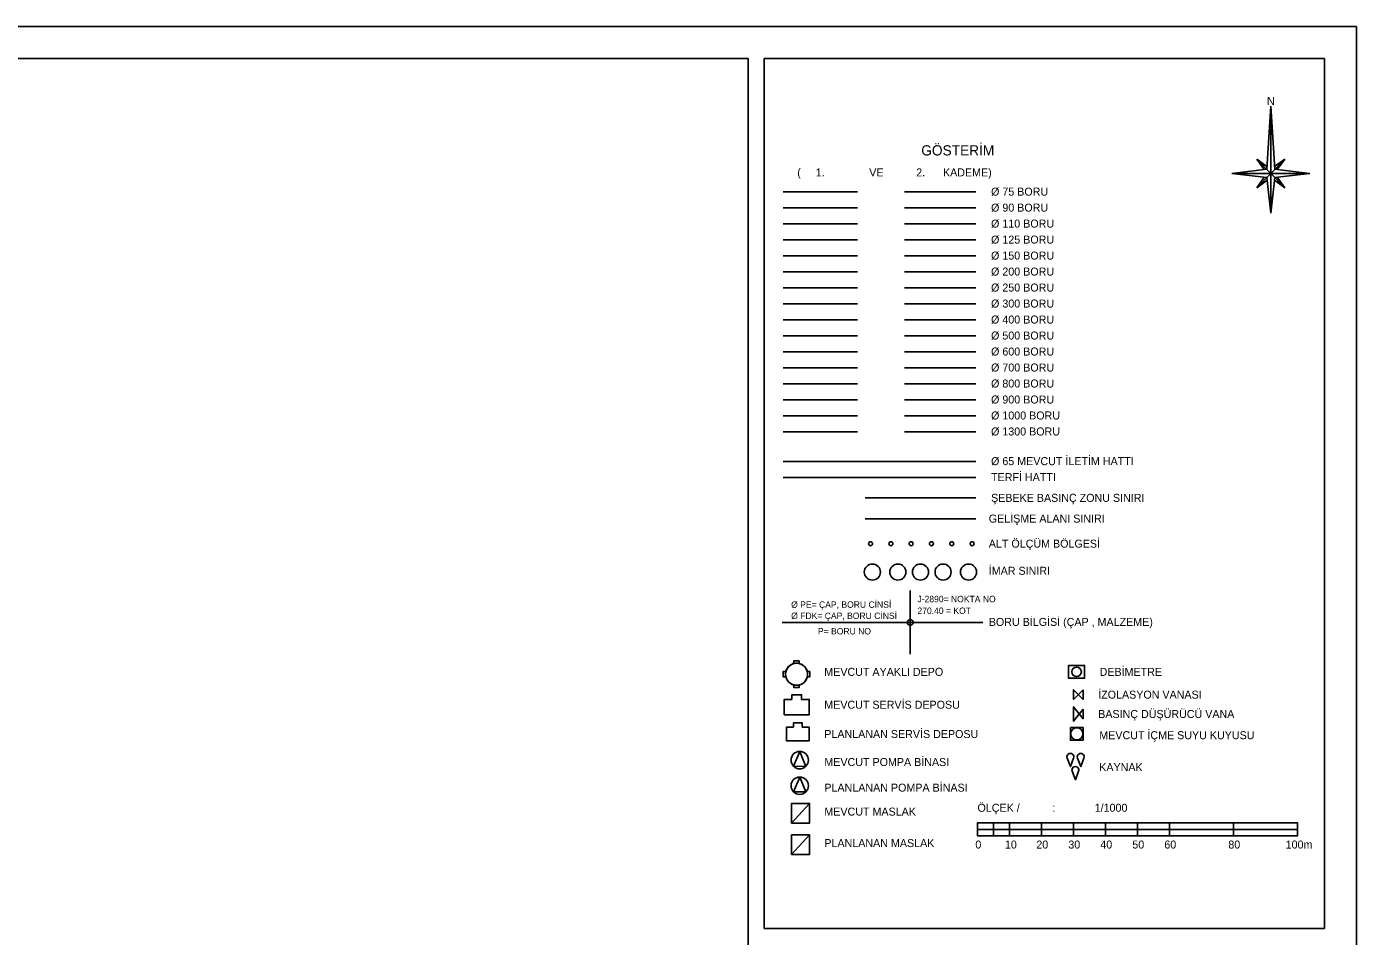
# Model space of a CAD drawing. Extents: x 314 to 1145, y -10 to 574.
# Drawn here: x 729.5 to 1145, y 289.5 to 574 of the extents above; entities that cross this region are included whole.
import ezdxf

# ---------------------------------------------------------------- set-up
doc = ezdxf.new("R2010")
doc.units = 0
for name, color, linetype in [('00-SERVIS_DEPO', 7, 'Continuous'), ('00_ALT_BOLGE_SINIRI', 7, 'Continuous'), ('00_GELISME_SINIRI', 7, 'Continuous'), ('00_IMAR SINIRI', 7, 'Continuous'), ('00_KAYNAK', 7, 'Continuous'), ('00_MASLAK', 7, 'Continuous'), ('00_MEVCUT ILETIM HATTI', 7, 'Continuous'), ('00_TERFİ HATTI', 7, 'Continuous'), ('00_TM', 7, 'Continuous'), ('00_VANA', 7, 'Continuous'), ('01_BORU_75', 7, 'Continuous'), ('02_BORU_100', 7, 'Continuous'), ('03_BORU_150', 7, 'Continuous'), ('04_BORU_200', 7, 'Continuous'), ('05_BORU_250', 7, 'Continuous'), ('06_BORU_300', 7, 'Continuous'), ('07_BORU_400', 7, 'Continuous'), ('08_BORU_500', 7, 'Continuous'), ('09_BORU_600', 7, 'Continuous'), ('10_BORU_700', 7, 'Continuous'), ('11_BORU_800', 7, 'Continuous'), ('125_boru', 7, 'Continuous'), ('12_BORU_900', 7, 'Continuous'), ('13_BORU_1000', 7, 'Continuous'), ('14_BORU_1300', 7, 'Continuous'), ('BETON-25', 7, 'Continuous'), ('BETON-60', 7, 'Continuous'), ('Boru Bilgisi', 7, 'Continuous'), ('Default', 7, 'Continuous'), ('Lejand', 7, 'Continuous'), ('Level 50', 7, 'Continuous'), ('Level 51', 7, 'Continuous'), ('Level 52', 7, 'Continuous'), ('ScaleBar-20', 7, 'Continuous'), ('ScaleBar-25', 7, 'Continuous'), ('SEMBOL-10', 7, 'Continuous'), ('SEMBOL-30', 7, 'Continuous'), ('YAZI-25', 7, 'Continuous'), ('YAZI-40', 7, 'Continuous'), ('ŞEBEKE BASINC ZON SINIRI', 7, 'Continuous')]:
    doc.layers.add(name, color=color, linetype=linetype)

# ---------------------------------------------------------------- blocks, each defined once
blk = doc.blocks.new('junction_1')
at = {"layer": '00_NODE'}
for start, end in [(45, 225), (45, 225), (225, 45), (225, 45)]:
    blk.add_arc((0, -0.02), 0.914, start, end, dxfattribs=at)
blk = doc.blocks.new('junction_2')
at = {"layer": 'Default'}
blk.add_blockref('junction_1', (0, 0), dxfattribs=at)
blk = doc.blocks.new('A$C32CF5DD8')
at = {"layer": '00_KAYNAK'}
for points in [[(35, 179), (0, 264), (-30, 179)], [(-30, 179), (0, 264), (35, 179)], [(-20, 47), (-54, 132), (-84, 47)], [(-84, 47), (-54, 132), (-20, 47)], [(84, 47), (49, 132), (20, 47)], [(20, 47), (49, 132), (84, 47)]]:
    blk.add_lwpolyline(points, dxfattribs=at)
for centre in [(2, 167), (2, 167), (-52, 35), (-52, 35), (52, 35), (52, 35)]:
    blk.add_arc(centre, 34.6, 159.3514, 20.6486, dxfattribs=at)

msp = doc.modelspace()

# ---------------------------------------------------------------- linework, layer by layer
at = {"layer": '00-SERVIS_DEPO'}
for p, q in [((969.27, 374.86), (969.27, 375.68)), ((969.27, 375.68), (970.87, 375.68)), ((970.87, 374.86), (970.87, 375.68)), ((965.89, 372.29), (966.7, 372.29)), ((965.89, 370.69), (965.89, 372.29)), ((965.89, 370.69), (966.7, 370.69)), ((973.44, 372.29), (974.26, 372.29)), ((973.44, 370.69), (974.26, 370.69)), ((974.26, 372.29), (974.26, 370.69)), ((969.27, 367.31), (969.27, 368.13)), ((969.27, 367.31), (970.87, 367.31)), ((970.87, 367.31), (970.87, 368.13))]:
    msp.add_line(p, q, dxfattribs=at)
for points in [[(970.87, 375.68), (969.27, 375.68), (969.27, 374.86)], [(970.87, 374.86), (970.87, 375.68)], [(966.7, 372.29), (965.89, 372.29), (965.89, 370.69), (966.7, 370.69)], [(974.26, 372.29), (973.44, 372.29)], [(973.44, 370.69), (974.26, 370.69), (974.26, 372.29)], [(969.27, 368.13), (969.27, 367.31), (970.87, 367.31), (970.87, 368.13)], [(968.62, 363.6), (966.24, 363.6), (966.24, 358.79), (974.03, 358.79), (974.03, 363.6), (971.65, 363.6), (971.65, 365.07), (968.62, 365.07), (968.62, 363.6)], [(968.62, 363.6), (966.24, 363.6), (966.24, 358.79), (974.03, 358.79), (974.03, 363.6), (971.65, 363.6), (971.65, 365.07), (968.62, 365.07), (968.62, 363.6)], [(969.11, 354.95), (966.97, 354.95), (966.97, 350.62), (973.98, 350.62), (973.98, 354.95), (971.84, 354.95), (971.84, 356.28), (969.11, 356.28), (969.11, 354.95)]]:
    msp.add_lwpolyline(points, dxfattribs=at)
msp.add_circle((970.07, 371.49), 3.46, dxfattribs=at)
for start, end in [(13.3637, 180), (76.6363, 103.3637), (166.6363, 180), (180, 193.3637), (180, 193.3637), (193.3637, 360), (360, 13.3637), (360, 13.3637), (346.6363, 0), (256.6363, 283.3637)]:
    msp.add_arc((970.07, 371.49), 3.46, start, end, dxfattribs=at)
at = {"layer": '00_ALT_BOLGE_SINIRI'}
for centre, start, end in [((993.19, 412.29), 0, 180), ((993.19, 412.29), 180, 0), ((999.54, 412.29), 0, 180), ((999.54, 412.29), 180, 0), ((1005.88, 412.29), 0, 180), ((1005.88, 412.29), 180, 0), ((1012.23, 412.29), 0, 180), ((1012.23, 412.29), 180, 0), ((1018.58, 412.29), 0, 180), ((1018.58, 412.29), 180, 0), ((1024.93, 412.29), 0, 180), ((1024.93, 412.29), 180, 0)]:
    msp.add_arc(centre, 0.625, start, end, dxfattribs=at)
at = {"layer": '00_GELISME_SINIRI'}
msp.add_line((991.47, 420.1), (1026.14, 420.1), dxfattribs=at)
at = {"layer": '00_IMAR SINIRI'}
for centre in [(993.77, 403.43), (1001.73, 403.43), (1008.79, 403.43), (1015.86, 403.43), (1023.82, 403.43)]:
    msp.add_circle(centre, 2.52, dxfattribs=at)
at = {"layer": '00_MASLAK'}
for p, q in [((974.12, 331.1), (968.54, 324.96)), ((968.54, 324.96), (974.12, 331.1)), ((968.54, 315.12), (974.12, 321.26))]:
    msp.add_line(p, q, dxfattribs=at)
msp.add_lwpolyline([(968.54, 324.96), (974.12, 324.96), (974.12, 331.1)], dxfattribs=at)
for points in [[(968.54, 324.96), (974.12, 324.96), (974.12, 331.1), (968.54, 331.1)], [(968.54, 315.12), (974.12, 315.12), (974.12, 321.26), (968.54, 321.26)]]:
    msp.add_lwpolyline(points, close=True, dxfattribs=at)
at = {"layer": '00_MEVCUT ILETIM HATTI'}
msp.add_line((965.89, 438.05), (1026.14, 438.05), dxfattribs=at)
at = {"layer": '00_TERFİ HATTI'}
msp.add_line((965.89, 433.05), (1026.14, 433.05), dxfattribs=at)
at = {"layer": '00_TM'}
for points in [[(972.98, 342.68), (971.05, 347.36), (969.12, 342.72), (972.98, 342.68)], [(972.98, 342.68), (971.05, 347.36), (969.12, 342.72), (972.98, 342.68)], [(972.98, 334.67), (971.05, 339.35), (969.12, 334.71), (972.98, 334.67)]]:
    msp.add_lwpolyline(points, dxfattribs=at)
for centre in [(971.07, 344.63), (971.07, 336.62)]:
    msp.add_circle(centre, 2.73, dxfattribs=at)
at = {"layer": '00_VANA'}
for points in [[(1059.62, 366.61), (1056.62, 363.61), (1056.62, 366.61), (1059.62, 363.61), (1059.62, 366.61)], [(1059.62, 360.55), (1056.62, 356.8), (1056.62, 361.3), (1059.62, 357.55), (1059.62, 360.55)]]:
    msp.add_lwpolyline(points, dxfattribs=at)
at = {"layer": '01_BORU_75'}
for p, q in [((965.89, 522.33), (989.08, 522.33)), ((1003.79, 522.33), (1026.14, 522.33))]:
    msp.add_line(p, q, dxfattribs=at)
at = {"layer": '02_BORU_100'}
for p, q in [((965.89, 517.33), (989.08, 517.33)), ((1003.79, 517.33), (1026.14, 517.33)), ((965.89, 512.33), (989.08, 512.33)), ((1003.79, 512.33), (1026.14, 512.33))]:
    msp.add_line(p, q, dxfattribs=at)
at = {"layer": '03_BORU_150'}
for p, q in [((965.89, 502.33), (989.08, 502.33)), ((1003.79, 502.33), (1026.14, 502.33))]:
    msp.add_line(p, q, dxfattribs=at)
at = {"layer": '04_BORU_200'}
for p, q in [((965.89, 497.33), (989.08, 497.33)), ((1003.79, 497.33), (1026.14, 497.33))]:
    msp.add_line(p, q, dxfattribs=at)
at = {"layer": '05_BORU_250'}
for p, q in [((965.89, 492.33), (989.08, 492.33)), ((1003.79, 492.33), (1026.14, 492.33))]:
    msp.add_line(p, q, dxfattribs=at)
at = {"layer": '06_BORU_300'}
for p, q in [((965.89, 487.33), (989.08, 487.33)), ((1003.79, 487.33), (1026.14, 487.33))]:
    msp.add_line(p, q, dxfattribs=at)
at = {"layer": '07_BORU_400'}
for p, q in [((965.89, 482.33), (989.08, 482.33)), ((1003.79, 482.33), (1026.14, 482.33))]:
    msp.add_line(p, q, dxfattribs=at)
at = {"layer": '08_BORU_500'}
for p, q in [((965.89, 477.33), (989.08, 477.33)), ((1003.79, 477.33), (1026.14, 477.33))]:
    msp.add_line(p, q, dxfattribs=at)
at = {"layer": '09_BORU_600'}
for p, q in [((965.89, 472.33), (989.08, 472.33)), ((1003.79, 472.33), (1026.14, 472.33))]:
    msp.add_line(p, q, dxfattribs=at)
at = {"layer": '10_BORU_700'}
for p, q in [((965.89, 467.33), (989.08, 467.33)), ((1003.79, 467.33), (1026.14, 467.33))]:
    msp.add_line(p, q, dxfattribs=at)
at = {"layer": '11_BORU_800'}
for p, q in [((965.89, 462.33), (989.08, 462.33)), ((1003.79, 462.33), (1026.14, 462.33))]:
    msp.add_line(p, q, dxfattribs=at)
at = {"layer": '125_boru'}
for p, q in [((965.89, 507.33), (989.08, 507.33)), ((1003.79, 507.33), (1026.14, 507.33))]:
    msp.add_line(p, q, dxfattribs=at)
at = {"layer": '12_BORU_900'}
for p, q in [((965.89, 457.33), (989.08, 457.33)), ((1003.79, 457.33), (1026.14, 457.33))]:
    msp.add_line(p, q, dxfattribs=at)
at = {"layer": '13_BORU_1000'}
for p, q in [((965.89, 452.33), (989.08, 452.33)), ((1003.79, 452.33), (1026.14, 452.33))]:
    msp.add_line(p, q, dxfattribs=at)
at = {"layer": '14_BORU_1300'}
for p, q in [((965.89, 447.33), (989.08, 447.33)), ((1003.79, 447.33), (1026.14, 447.33))]:
    msp.add_line(p, q, dxfattribs=at)
at = {"layer": 'BETON-25'}
msp.add_lwpolyline([(1055.06, 374.23), (1060.06, 374.23), (1060.06, 370.23), (1055.06, 370.23)], close=True, dxfattribs=at)
msp.add_circle((1057.56, 372.23), 1.5, dxfattribs=at)
at = {"layer": 'BETON-60'}
for p, q in [((1005.58, 387.71), (1005.58, 397.71)), ((965.57, 387.71), (1005.58, 387.71)), ((1005.58, 377.71), (1005.58, 387.71)), ((1028.23, 387.71), (1005.58, 387.71))]:
    msp.add_line(p, q, dxfattribs=at)
at = {"layer": 'Lejand'}
for p, q in [((1118.22, 549.07), (1116.97, 529.37)), ((1118.22, 549.07), (1119.47, 529.37)), ((1118.22, 549.07), (1118.22, 515.64)), ((1113.84, 532.58), (1117.03, 530.22)), ((1116.17, 529.27), (1113.84, 532.58)), ((1113.84, 532.58), (1118.22, 528.09)), ((1122.6, 532.58), (1118.22, 528.09)), ((1122.6, 532.58), (1119.42, 530.22)), ((1120.27, 529.27), (1122.6, 532.58)), ((1106.03, 528.09), (1116.97, 529.37)), ((1118.22, 528.09), (1106.03, 528.09)), ((1106.03, 528.09), (1116.97, 526.81)), ((1113.84, 523.6), (1118.22, 528.09)), ((1122.6, 523.6), (1118.22, 528.09)), ((1118.22, 528.09), (1130.41, 528.09)), ((1130.35, 528.09), (1119.47, 529.37)), ((1130.35, 528.09), (1119.47, 526.81)), ((1116.17, 526.9), (1113.84, 523.6)), ((1113.84, 523.6), (1117.07, 525.99)), ((1116.97, 526.81), (1118.22, 515.64)), ((1119.47, 526.81), (1118.22, 515.64)), ((1122.6, 523.6), (1119.38, 525.99)), ((1120.27, 526.9), (1122.6, 523.6))]:
    msp.add_line(p, q, dxfattribs=at)
at = {"layer": 'Level 50'}
msp.add_lwpolyline([(324, 0), (955, 0), (955, 564), (324, 564)], close=True, dxfattribs=at)
at = {"layer": 'Level 51'}
msp.add_lwpolyline([(314, -10), (1145, -10), (1145, 574), (314, 574)], close=True, dxfattribs=at)
at = {"layer": 'Level 52'}
msp.add_lwpolyline([(960, 292), (1135, 292), (1135, 564), (960, 564)], close=True, dxfattribs=at)
at = {"layer": 'ScaleBar-20'}
for p, q in [((1031.61, 324.98), (1031.61, 320.98)), ((1036.61, 324.98), (1036.61, 320.98)), ((1046.61, 324.98), (1046.61, 320.98)), ((1056.61, 324.98), (1056.61, 320.98)), ((1066.61, 324.98), (1066.61, 320.98)), ((1076.61, 324.98), (1076.61, 320.98)), ((1086.61, 324.98), (1086.61, 320.98)), ((1106.61, 324.98), (1106.61, 320.98)), ((1026.61, 322.98), (1126.61, 322.98))]:
    msp.add_line(p, q, dxfattribs=at)
for points in [[(1026.61, 324.98), (1026.61, 322.98), (1031.61, 322.98), (1031.61, 324.98)], [(1036.61, 324.98), (1036.61, 322.98), (1046.61, 322.98), (1046.61, 324.98)], [(1056.61, 324.98), (1056.61, 322.98), (1066.61, 322.98), (1066.61, 324.98)], [(1076.61, 324.98), (1076.61, 322.98), (1086.61, 322.98), (1086.61, 324.98)], [(1106.61, 324.98), (1106.61, 322.98), (1126.61, 322.98), (1126.61, 324.98)], [(1031.61, 322.98), (1031.61, 320.98), (1036.61, 320.98), (1036.61, 322.98)], [(1046.61, 322.98), (1046.61, 320.98), (1056.61, 320.98), (1056.61, 322.98)], [(1066.61, 322.98), (1066.61, 320.98), (1076.61, 320.98), (1076.61, 322.98)], [(1086.61, 322.98), (1086.61, 320.98), (1106.61, 320.98), (1106.61, 322.98)]]:
    msp.add_lwpolyline(points, close=True, dxfattribs=at)
at = {"layer": 'ScaleBar-25'}
msp.add_lwpolyline([(1126.61, 324.98), (1026.61, 324.98), (1026.61, 320.98), (1126.61, 320.98)], close=True, dxfattribs=at)
at = {"layer": 'SEMBOL-10'}
msp.add_circle((1057.62, 352.84), 1.9, dxfattribs=at)
msp.add_circle((1057.62, 352.84), 1.9, dxfattribs=at)
at = {"layer": 'SEMBOL-30'}
msp.add_lwpolyline([(1055.62, 354.84), (1055.62, 350.84), (1059.62, 350.84), (1059.62, 354.84)], close=True, dxfattribs=at)
at = {"layer": 'ŞEBEKE BASINC ZON SINIRI'}
msp.add_line((991.47, 426.64), (1026.14, 426.64), dxfattribs=at)

# ---------------------------------------------------------------- block references
at = {"layer": 'Default'}
msp.add_blockref('junction_2', (1005.58, 387.71), dxfattribs=at)
at = {"layer": 'Default', "xscale": 0.03125, "yscale": 0.03125, "rotation": 180}
msp.add_blockref('A$C32CF5DD8', (1057.25, 346.74), dxfattribs=at)

# ---------------------------------------------------------------- texts
at = {"layer": 'Boru Bilgisi'}
for s, height, p in [('%%C PE= ÇAP, BORU CİNSİ', 2.0003, (968.4, 392.25)), ('J-2890= NOKTA NO', 2.0003, (1007.84, 394)), ('%%C FDK= ÇAP, BORU CİNSİ', 2.0003, (968.4, 388.76)), ('270.40 = KOT', 2.0003, (1007.84, 390.34)), ('P= BORU NO', 2, (976.76, 383.93))]:
    msp.add_text(s, height=height, dxfattribs=at).set_placement(p)
at = {"layer": 'Lejand'}
msp.add_text('N', height=2.56, dxfattribs=at).set_placement((1117.02, 549.47))
at = {"layer": 'ScaleBar-25'}
for s, p in [('ÖLÇEK /           :', (1026.61, 328.48)), ('  1/1000', (1061.37, 328.48)), ('0', (1025.94, 316.98)), ('10', (1035.18, 316.98)), ('20', (1044.99, 316.98)), ('30', (1054.99, 316.98)), ('40', (1064.99, 316.98)), ('50', (1074.99, 316.98)), ('60', (1084.99, 316.98)), ('80', (1104.99, 316.98)), ('100m', (1122.89, 316.98))]:
    msp.add_text(s, height=2.5, dxfattribs=at).set_placement(p)
at = {"layer": 'YAZI-25'}
for s, p in [('(     1.               VE           2.      KADEME)', (970.31, 527.15)), ('%%C 75 BORU', (1030.85, 521.14)), ('%%C 90 BORU', (1030.85, 516.14)), ('%%C 110 BORU', (1030.85, 511.14)), ('%%C 125 BORU', (1030.85, 506.14)), ('%%C 150 BORU', (1030.85, 501.14)), ('%%C 200 BORU', (1030.85, 496.14)), ('%%C 250 BORU', (1030.85, 491.14)), ('%%C 300 BORU', (1030.85, 486.14)), ('%%C 400 BORU', (1030.85, 481.14)), ('%%C 500 BORU', (1030.85, 476.14)), ('%%C 600 BORU', (1030.85, 471.14)), ('%%C 700 BORU', (1030.85, 466.14)), ('%%C 800 BORU', (1030.85, 461.14)), ('%%C 900 BORU', (1030.85, 456.14)), ('%%C 1000 BORU', (1030.85, 451.14)), ('%%C 1300 BORU', (1030.85, 446.14)), ('%%C 65 MEVCUT İLETİM HATTI', (1030.85, 436.86)), ('TERFİ HATTI', (1030.85, 431.86)), ('ŞEBEKE BASINÇ ZONU SINIRI', (1030.85, 425.39)), ('GELİŞME ALANI SINIRI', (1030.14, 418.9)), ('ALT ÖLÇÜM BÖLGESİ', (1030.14, 411.07)), ('İMAR SINIRI', (1030.14, 402.58)), ('BORU BİLGİSİ (ÇAP , MALZEME)', (1030.14, 386.59)), ('DEBİMETRE', (1064.77, 370.98)), ('MEVCUT AYAKLI DEPO', (978.74, 370.98)), ('İZOLASYON VANASI', (1064.33, 363.86)), ('MEVCUT SERVİS DEPOSU', (978.74, 360.7)), ('BASINÇ DÜŞÜRÜCÜ VANA', (1064.33, 357.8)), ('PLANLANAN SERVİS DEPOSU', (978.74, 351.54)), ('MEVCUT İÇME SUYU KUYUSU', (1064.67, 351.17)), ('MEVCUT POMPA BİNASI', (978.76, 342.78)), ('KAYNAK', (1064.65, 341.18)), ('PLANLANAN POMPA BİNASI', (978.76, 334.77)), ('MEVCUT MASLAK', (978.76, 327.28)), ('PLANLANAN MASLAK', (978.76, 317.44))]:
    msp.add_text(s, height=2.5, dxfattribs=at).set_placement(p)
at = {"layer": 'YAZI-40'}
msp.add_text(' GÖSTERİM ', height=3.2, dxfattribs=at).set_placement((1007.85, 533.69))

doc.saveas('drawing.dxf')
